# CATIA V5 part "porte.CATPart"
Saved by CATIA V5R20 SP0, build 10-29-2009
Part number: porte
Bounding box of the stored display mesh (mm): x -40 to 0, y 0 to 270, z 0 to 360
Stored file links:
  C:\Users\bensf\Desktop\bouthaina\porte.CATPart
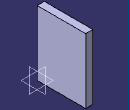
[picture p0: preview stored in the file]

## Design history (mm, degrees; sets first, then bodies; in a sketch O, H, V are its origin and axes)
Body1 (main body)
  Sketch1 on yz-plane, origin (0, 0, 0), H (0, 1, 0), V (0, 0, 1)
    line L1 (0, 0) -> (270, 0)
    line L2 (270, 0) -> (270, 360)
    line L3 (270, 360) -> (0, 360)
    line L4 (0, 360) -> (0, 0)
    length L4 = 360
    length L1 = 270
    horizontal: L1 H, L3 H
    vertical: L2 V, L4 V
  Pad1: profile Sketch1, direction (-1, 0, 0), length 40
